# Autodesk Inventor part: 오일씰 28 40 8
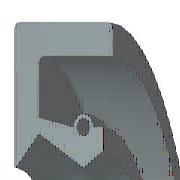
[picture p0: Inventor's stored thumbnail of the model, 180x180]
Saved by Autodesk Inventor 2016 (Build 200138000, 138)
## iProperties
IsCustomPart: 1
Created: 2012-02
Part Number: 오일씰 28 40 8
Material: 고무
Description: Oil-seal
Document SubType Name: Modeling
Standard: KS B 2804
Designer: mduedu
Standards Organization: KS
Language: en-US
Size Designation: D - 28 40 8
Categories: <MemberInstance><Categories><Category DisplayName="Shaft Parts" InternalName="7f7aeb1f-a693-4053-b835-cee3144e0d98" Mnemonic="SHFT"><Category DisplayName="Seali
Density: 0.93 g/cm^3
Mass: 2.83894 g
Surface Area: 40.7521 cm^2
Volume: 3.05262 cm^3
Appearance: 고무 - 검은색 - 버전 1.1
Author: mduedu
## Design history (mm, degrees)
sketch "Sketch1"
  geometry: L1 (0, 20)-(8, 20); L2 (8, 18.25)-(1.75, 18.25); L3 (1.75, 15.75)-(4.9, 14); L4 (4.9, 14)-(0, 14); L5 (0, 0)-(9.586, 0) reference; L6 (4.9, 14)-(6.3, 14.875); L7 (0, 18)-(0, -3) reference; L8 (-1.941, 0)-(11.507, 0) reference; L9 (4.2, 16.1)-(1.75, 16.71); L10 (1.75, 16.71)-(1.75, 18.25); L11 (0, 20)-(0, 14.088); L12 (4.9, 14)-(0, 14); L13 (1.75, 15.75)-(0.152, 14.028); L14 (8, 20)-(8, 18.25); L15 (5.6, 16.1)-(6.3, 16.1); L16 (6.3, 16.1)-(6.3, 14.875); C1 r 0.455 at (4.9, 16.1); A1 r 0.7 centre (4.9, 16.1) between (5.6, 16.1) and (4.2, 16.1); A2 r 0.088 centre (0.087, 14.088) between (0, 14.088) and (0.152, 14.028); 1 further point
  constraints: 28 end point, 5 horizontal alignment, 5 point on line, 4 point on circle, 4 vertical alignment, 3 centre point, 3 tangent, 2 collinear, 2 horizontal, 2 perpendicular, 1 coincident, 1 parallel
  dimensions: "d0" = 40 diameter of L1 L5 (= SD2); "d1" = 1.75 distance of L1.end L2.start (= SD); "d2" = 0.91 diameter of C1 (= SPDI); "d3" = 1.4 diameter of A1 (= SPDA); "d4" = 28 diameter of L3.end L5 (= NND); "d5" = 31.5 diameter of L3.start L5 (= TKDM); "d7" = 33.42 diameter of L9.end L5 (= TKDM + 0.24 x SWDT); "d8" = 1.75 distance between parallel lines of L11 L10 (= SD); "d9" = 4.9 distance from line of L11 C1.centre (= SPDST); "d10" = 32.2 diameter of C1.centre L5 (= HLDM); "d11" = 0.0875 radius of A2 (= 0.25 x LAB); "d12" = 6.3 distance between parallel lines of L11 L16 (= SDI); "d13" = 29.75 diameter of L6.end L5 (= ABDM); "d14" = 8 distance from line of L11 L1.end (= SWDT)
revolve "Body" stored, may be unused: angle "d17" = 90 deg
revolve "Spring1" stored, may be unused: angle "d18" = 90 deg
fillet "Fillet1" dims "d6" = 0.4 (= RR)
body "Solid1"
other parameters: "SD2" = 40 [user parameter; used in 1 equation term], "SWDT" = 8 [user parameter; used in 2 equation terms], "RR" = 0.4 [user parameter; used in 1 equation term], "SD" = 1.75 [user parameter; used in 2 equation terms], "NND" = 28 [user parameter; used in 1 equation term], "SPDA" = 1.4 [user parameter; used in 1 equation term], "SPDI" = 0.91 [user parameter; used in 1 equation term], "TKDM" = 31.5 [user parameter; used in 2 equation terms], "HLDM" = 32.2 [user parameter; used in 1 equation term], "ABDM" = 29.75 [user parameter; used in 1 equation term], "SDI" = 6.3 [user parameter; used in 1 equation term], "SPDST" = 4.9 [user parameter; used in 1 equation term], "LAB" = 0.35 [user parameter; used in 1 equation term], "d15" = 0, "d16" = 0, "d19" = 0
